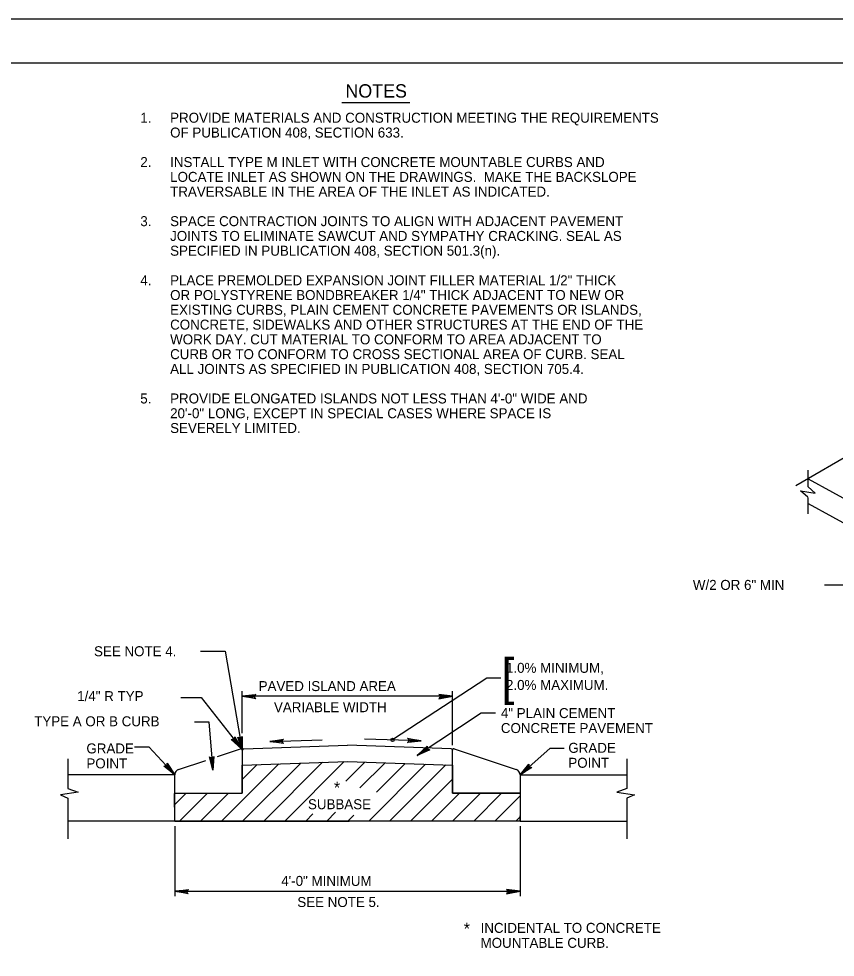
# Model space of a CAD drawing. Extents: x 638443 to 639347, y 298415 to 299009.
# Drawn here: x 638698.3 to 638973.2, y 298692.8 to 299008.7 of the extents above; entities that cross this region are included whole.
import ezdxf

# ---------------------------------------------------------------- set-up
doc = ezdxf.new("R2010")
doc.units = 0
for name, color, linetype in [('1', 7, 'Continuous'), ('2', 7, 'Continuous'), ('3', 7, 'Continuous'), ('PLT-BNDY', 7, 'Continuous')]:
    doc.layers.add(name, color=color, linetype=linetype)

msp = doc.modelspace()

# ---------------------------------------------------------------- linework, layer by layer
at = {"layer": '1'}
msp.add_line((639268.08, 298993.73), (638482.08, 298993.73), dxfattribs=at)
msp.add_lwpolyline([(638963.98, 298847.69), (638961.51, 298849.8), (638966.47, 298849), (638964.07, 298851.19)], dxfattribs=at)
at = {"layer": '2'}
for p, q in [((638980.79, 298863.58), (638959.89, 298851.51)), ((638964.03, 298851.21), (638964.03, 298856.81)), ((638964.03, 298853.9), (639006.65, 298830.46)), ((638964.03, 298842.1), (638964.03, 298847.54)), ((638964.1, 298845.54), (638980.67, 298836.43)), ((638976.45, 298818.03), (638969.52, 298818.03)), ((638759.52, 298795.78), (638767.74, 298795.78)), ((638767.74, 298795.78), (638773.54, 298762.52)), ((638855.83, 298786.76), (638824.12, 298765.93)), ((638860.63, 298786.76), (638855.83, 298786.76)), ((638773.54, 298768.28), (638773.54, 298782.36)), ((638844.3, 298764.2), (638844.3, 298782.36)), ((638752.85, 298780.27), (638759.75, 298780.27)), ((638759.75, 298780.27), (638773.23, 298762.97)), ((638818.22, 298780.68), (638773.54, 298780.68)), ((638844.3, 298780.68), (638818.22, 298780.68)), ((638782.83, 298765.38), (638800.39, 298765.96)), ((638833.74, 298765.61), (638814.73, 298766.25)), ((638765.18, 298760.39), (638772.92, 298762.97)), ((638773.54, 298762.52), (638773.54, 298748.01)), ((638774.01, 298763), (638808.92, 298764.17)), ((638843.83, 298763), (638808.92, 298764.17)), ((638844.3, 298748.01), (638844.3, 298762.52)), ((638844.92, 298762.97), (638865.75, 298756.02)), ((638714.79, 298759.54), (638714.79, 298749.63)), ((638752.09, 298756.02), (638761.23, 298759.07)), ((638903.05, 298759.54), (638903.05, 298749.63)), ((638766.59, 298738.62), (638785.89, 298757.92)), ((638773.54, 298752.65), (638778.57, 298757.67)), ((638773.66, 298738.62), (638793.2, 298758.16)), ((638780.74, 298738.62), (638800.52, 298758.41)), ((638787.81, 298738.62), (638807.83, 298758.65)), ((638808.35, 298752.09), (638814.75, 298758.49)), ((638813.1, 298749.77), (638821.59, 298758.26)), ((638816.09, 298738.62), (638835.28, 298757.81)), ((638818.78, 298748.38), (638828.43, 298758.03)), ((638823.16, 298738.62), (638842.12, 298757.58)), ((638750.79, 298754.22), (638714.79, 298754.22)), ((638750.79, 298740.42), (638750.79, 298754.22)), ((638773.54, 298752.64), (638773.71, 298752.81)), ((638830.23, 298738.62), (638844.3, 298752.69)), ((638867.05, 298754.22), (638903.05, 298754.22)), ((638867.05, 298754.22), (638867.05, 298748.01)), ((638714.79, 298746.32), (638714.79, 298732.63)), ((638773.54, 298748.01), (638750.76, 298747.95)), ((638750.79, 298744.19), (638754.57, 298747.96)), ((638752.45, 298738.62), (638761.81, 298747.98)), ((638759.52, 298738.62), (638768.89, 298747.99)), ((638837.3, 298738.62), (638846.69, 298748.01)), ((638867.05, 298748.01), (638844.3, 298748.01)), ((638844.37, 298738.62), (638853.76, 298748.01)), ((638851.45, 298738.62), (638860.83, 298748.01)), ((638858.52, 298738.62), (638867.05, 298747.15)), ((638903.05, 298746.32), (638903.05, 298732.63)), ((638750.79, 298738.62), (638750.79, 298740.42)), ((638794.88, 298738.62), (638797.31, 298741.05)), ((638801.95, 298738.62), (638804.93, 298741.6)), ((638809.02, 298738.62), (638811.07, 298740.67)), ((638865.59, 298738.62), (638867.05, 298740.08)), ((638867.05, 298738.62), (638867.05, 298740.42)), ((638750.79, 298738.62), (638714.79, 298738.62)), ((638750.79, 298738.62), (638809.54, 298738.62)), ((638750.79, 298736.94), (638750.79, 298713.31)), ((638867.05, 298738.62), (638808.3, 298738.62)), ((638867.05, 298738.62), (638903.05, 298738.62)), ((638867.05, 298736.94), (638867.05, 298713.31)), ((638750.79, 298714.99), (638818.22, 298714.99)), ((638818.22, 298714.99), (638867.05, 298714.99))]:
    msp.add_line(p, q, dxfattribs=at)
for points in [[(638777.89, 298780.02), (638777.73, 298780.34), (638773.54, 298780.68), (638777.89, 298780.02), (638778.11, 298779.83), (638773.54, 298780.68), (638777.74, 298780.78), (638777.9, 298781.09), (638773.54, 298780.68), (638778.14, 298781.29), (638777.9, 298781.09)], [(638839.95, 298780.02), (638840.11, 298780.34), (638844.3, 298780.68), (638839.95, 298780.02), (638839.73, 298779.83), (638844.3, 298780.68), (638840.1, 298780.78), (638839.94, 298781.09), (638844.3, 298780.68), (638839.7, 298781.29), (638839.94, 298781.09)], [(638858.82, 298774.92), (638854.02, 298774.92), (638832.42, 298760.67)], [(638757.48, 298771.99), (638762.28, 298771.99), (638763.6, 298755.75)], [(638770.99, 298766.73), (638770.83, 298766.41), (638773.23, 298762.97), (638770.99, 298766.73), (638771, 298767.03), (638773.23, 298762.97), (638770.49, 298766.14), (638770.15, 298766.07), (638773.23, 298762.97), (638769.83, 298766.13), (638770.15, 298766.07)], [(638773.33, 298766.9), (638773.05, 298766.68), (638773.54, 298762.52), (638773.33, 298766.9), (638773.49, 298767.16), (638773.54, 298762.52), (638772.62, 298766.61), (638772.28, 298766.71), (638773.54, 298762.52), (638772.03, 298766.91), (638772.28, 298766.71)], [(638787.21, 298764.98), (638787.03, 298765.29), (638782.83, 298765.38), (638787.21, 298764.98), (638787.44, 298764.79), (638782.83, 298765.38), (638787.02, 298765.72), (638787.16, 298766.04), (638782.83, 298765.38), (638787.39, 298766.26), (638787.16, 298766.04)], [(638829.4, 298766.31), (638829.56, 298765.98), (638833.74, 298765.61), (638829.4, 298766.31), (638829.19, 298766.5), (638833.74, 298765.61), (638829.54, 298765.55), (638829.38, 298765.24), (638833.74, 298765.61), (638829.14, 298765.04), (638829.38, 298765.24)], [(638737.29, 298763.66), (638742.09, 298763.66), (638750.79, 298754.22)], [(638836.35, 298762.63), (638836.04, 298762.8), (638832.42, 298760.67), (638836.35, 298762.63), (638836.64, 298762.6), (638832.42, 298760.67), (638835.79, 298763.17), (638835.75, 298763.51), (638832.42, 298760.67), (638835.83, 298763.82), (638835.75, 298763.51)], [(638881.87, 298763.02), (638877.07, 298763.02), (638867.05, 298754.22)], [(638763.8, 298760.13), (638763.49, 298759.95), (638763.6, 298755.75), (638763.8, 298760.13), (638763.97, 298760.37), (638763.6, 298755.75), (638763.06, 298759.91), (638762.73, 298760.04), (638763.6, 298755.75), (638762.51, 298760.26), (638762.73, 298760.04)], [(638748.24, 298757.8), (638748.12, 298757.46), (638750.79, 298754.22), (638748.24, 298757.8), (638748.23, 298758.09), (638750.79, 298754.22), (638747.8, 298757.16), (638747.46, 298757.07), (638750.79, 298754.22), (638747.15, 298757.1), (638747.46, 298757.07)], [(638870.69, 298756.69), (638870.36, 298756.82), (638867.05, 298754.22), (638870.69, 298756.69), (638870.98, 298756.69), (638867.05, 298754.22), (638870.06, 298757.14), (638869.97, 298757.48), (638867.05, 298754.22), (638870.01, 298757.79), (638869.97, 298757.48)], [(638714.79, 298749.63), (638718.23, 298748.36), (638712.29, 298747.49), (638714.79, 298746.32)], [(638903.05, 298749.63), (638899.61, 298748.36), (638905.55, 298747.49), (638903.05, 298746.32)], [(638755.14, 298714.34), (638754.98, 298714.66), (638750.79, 298714.99), (638755.14, 298714.34), (638755.36, 298714.14), (638750.79, 298714.99), (638754.99, 298715.1), (638755.15, 298715.4), (638750.79, 298714.99), (638755.39, 298715.61), (638755.15, 298715.4)], [(638862.7, 298714.34), (638862.86, 298714.66), (638867.05, 298714.99), (638862.7, 298714.34), (638862.49, 298714.14), (638867.05, 298714.99), (638862.85, 298715.1), (638862.69, 298715.4), (638867.05, 298714.99), (638862.45, 298715.61), (638862.69, 298715.4)]]:
    msp.add_lwpolyline(points, dxfattribs=at)
msp.add_lwpolyline([(638750.79, 298738.62), (638750.76, 298747.95), (638773.54, 298748.01), (638773.54, 298757.51), (638808.92, 298758.69), (638844.3, 298757.51), (638844.3, 298748.01), (638867.05, 298748.01), (638867.05, 298738.62)], close=True, dxfattribs=at)
msp.add_circle((638824.12, 298765.93), 0.56, dxfattribs=at)
for centre, radius, start, end in [((638773.07, 298762.52), 0.474, 0, 108.4351), ((638774.02, 298762.52), 0.48, 91.9092, 180), ((638843.82, 298762.52), 0.48, 0, 88.0908), ((638844.77, 298762.52), 0.474, 71.5649, 180), ((638752.69, 298754.22), 1.9, 108.4349, 180), ((638865.15, 298754.22), 1.9, 0, 71.5651)]:
    msp.add_arc(centre, radius, start, end, dxfattribs=at)
at = {"layer": '3'}
msp.add_line((638807.08, 298980.54), (638829.94, 298980.54), dxfattribs=at)
at = {"layer": 'PLT-BNDY'}
msp.add_lwpolyline([(638443.08, 299008.73), (639284.08, 299008.73), (639284.08, 298414.73), (638443.08, 298414.73)], close=True, dxfattribs=at)

# ---------------------------------------------------------------- texts
at = {"layer": '1'}
for s, p in [('1. ', (638739.2, 298973.73)), ('PROVIDE MATERIALS AND CONSTRUCTION MEETING THE REQUIREMENTS', (638749.25, 298973.73)), ('OF PUBLICATION 408, SECTION 633.', (638749.25, 298968.75)), ('2.', (638739.2, 298958.81)), ('INSTALL TYPE M INLET WITH CONCRETE MOUNTABLE CURBS AND', (638749.25, 298958.81)), ('LOCATE INLET AS SHOWN ON THE DRAWINGS.  MAKE THE BACKSLOPE', (638749.25, 298953.83)), ('TRAVERSABLE IN THE AREA OF THE INLET AS INDICATED.', (638749.25, 298948.86)), ('3.', (638739.2, 298938.91)), ('SPACE CONTRACTION JOINTS TO ALIGN WITH ADJACENT PAVEMENT', (638749.25, 298938.91)), ('JOINTS TO ELIMINATE SAWCUT AND SYMPATHY CRACKING. SEAL AS', (638749.25, 298933.94)), ('SPECIFIED IN PUBLICATION 408, SECTION 501.3(n).', (638749.25, 298928.96)), ('4.', (638739.2, 298919.01)), ('PLACE PREMOLDED EXPANSION JOINT FILLER MATERIAL 1/2" THICK', (638749.25, 298919.01)), ('OR POLYSTYRENE BONDBREAKER 1/4" THICK ADJACENT TO NEW OR', (638749.25, 298914.04)), ('EXISTING CURBS, PLAIN CEMENT CONCRETE PAVEMENTS OR ISLANDS, ', (638749.25, 298909.07)), ('CONCRETE, SIDEWALKS AND OTHER STRUCTURES AT THE END OF THE', (638749.25, 298904.09)), ('WORK DAY. CUT MATERIAL TO CONFORM TO AREA ADJACENT TO ', (638749.25, 298899.12)), ('CURB OR TO CONFORM TO CROSS SECTIONAL AREA OF CURB. SEAL', (638749.25, 298894.14)), ('ALL JOINTS AS SPECIFIED IN PUBLICATION 408, SECTION 705.4.', (638749.25, 298889.17)), ('5.', (638739.2, 298879.22)), ('PROVIDE ELONGATED ISLANDS NOT LESS THAN 4\'-0" WIDE AND ', (638749.25, 298879.22)), ('20\'-0" LONG, EXCEPT IN SPECIAL CASES WHERE SPACE IS', (638749.25, 298874.25)), ('SEVERELY LIMITED.', (638749.25, 298869.28)), ('W/2 OR 6" MIN', (638925.25, 298816.46))]:
    msp.add_text(s, height=3.36, dxfattribs=at).set_placement(p)
at = {"layer": '3'}
for s, height, p in [('NOTES', 4.5, (638808.25, 298982.19)), ('SEE NOTE 4.', 3.36, (638723.63, 298794.13)), ('[', 12, (638860.71, 298781.36)), ('1.0% MINIMUM,', 3.36, (638862.33, 298788.54)), ('PAVED ISLAND AREA', 3.36, (638779.05, 298782.4)), ('2.0% MAXIMUM.', 3.36, (638862.33, 298782.78)), ('1/4" R TYP', 3.36, (638717.96, 298779.03)), ('VARIABLE WIDTH', 3.36, (638784.2, 298775.29)), ('4" PLAIN CEMENT ', 3.36, (638860.6, 298773.31)), ('TYPE A OR B CURB', 3.36, (638703.48, 298770.55)), ('CONCRETE PAVEMENT', 3.36, (638860.6, 298768.27)), ('GRADE', 3.36, (638721.06, 298761.41)), ('GRADE', 3.36, (638883.32, 298761.61)), ('POINT', 3.36, (638721.06, 298756.37)), ('POINT', 3.36, (638883.32, 298756.57)), ('*', 4.03, (638804.39, 298747.88)), ('SUBBASE', 3.36, (638795.66, 298742.63)), ('4\'-0" MINIMUM', 3.36, (638786.66, 298716.81)), ('SEE NOTE 5.', 3.36, (638792.07, 298709.7)), ('*', 4.03, (638848.12, 298700.41)), ('INCIDENTAL TO CONCRETE', 3.36, (638853.78, 298701)), ('MOUNTABLE CURB.', 3.36, (638853.78, 298695.96))]:
    msp.add_text(s, height=height, dxfattribs=at).set_placement(p)

doc.saveas('drawing.dxf')
